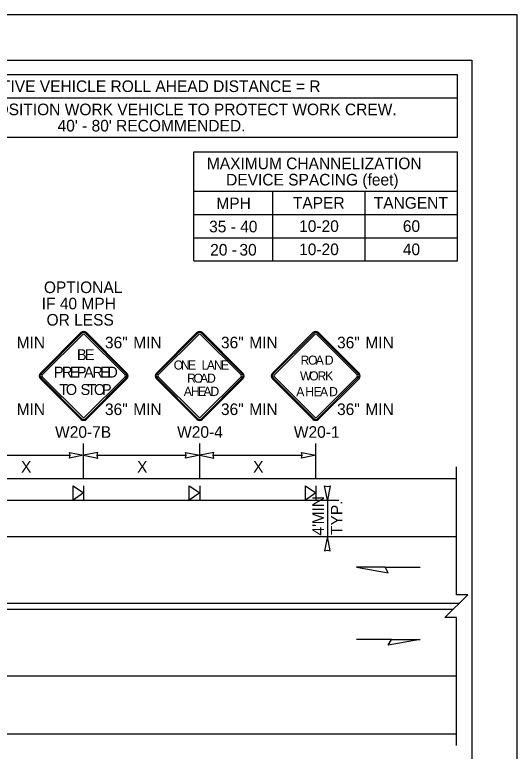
# Model space of a CAD drawing. Extents: x 99999.1 to 100095.7, y 99995 to 100010.7.
# Drawn here: x 100012.6 to 100016.06, y 100005.61 to 100010.69 of the extents above; entities that cross this region are included whole.
import ezdxf

# ---------------------------------------------------------------- set-up
doc = ezdxf.new("R2010")
doc.units = 0
for name, color, linetype in [('RD_ED_ShoulderPavedEdge', 7, 'Continuous'), ('RD_MK_LineDblYellowCenter', 7, 'Continuous'), ('RD_MK_LineEdgeWhite', 7, 'Continuous'), ('SH_GI_PlotLimits', 7, 'Continuous'), ('SH_GI_SheetBorder', 7, 'Continuous'), ('SH_TI_Tables', 7, 'Continuous'), ('TR_SN_ConstructionSigns', 7, 'Continuous'), ('TR_WZ_PortableSignMountBlk-Org', 7, 'Continuous'), ('TR_WZ_WorkZoneDetails', 7, 'Continuous'), ('TR_WZ_WorkZoneTextCurrent', 7, 'Continuous')]:
    doc.layers.add(name, color=color, linetype=linetype)

msp = doc.modelspace()

# ---------------------------------------------------------------- linework, layer by layer
at = {"layer": 'RD_ED_ShoulderPavedEdge'}
for p, q in [((100000.1076, 100007.4923), (100015.6424, 100007.4923)), ((100000.1076, 100005.7323), (100015.6424, 100005.7323))]:
    msp.add_line(p, q, dxfattribs=at)
at = {"layer": 'RD_MK_LineDblYellowCenter'}
for p, q in [((100012.2733, 100006.6323), (100015.6631, 100006.6323)), ((100012.2733, 100006.5923), (100015.6218, 100006.5923))]:
    msp.add_line(p, q, dxfattribs=at)
at = {"layer": 'RD_MK_LineEdgeWhite'}
for p, q in [((100000.1076, 100007.0923), (100015.6424, 100007.0923)), ((100000.1076, 100006.1323), (100015.6424, 100006.1323))]:
    msp.add_line(p, q, dxfattribs=at)
at = {"layer": 'SH_GI_PlotLimits'}
msp.add_lwpolyline([(99999.0625, 99999.6875), (100016.0625, 99999.6875), (100016.0625, 100010.6875), (99999.0625, 100010.6875)], close=True, dxfattribs=at)
at = {"layer": 'SH_GI_SheetBorder'}
for p, q in [((100000, 100010.375), (100015.75, 100010.375)), ((100015.75, 100010.375), (100015.75, 100000))]:
    msp.add_line(p, q, dxfattribs=at)
at = {"layer": 'SH_TI_Tables'}
for p, q in [((100011.4347, 100010.275), (100015.65, 100010.275)), ((100015.65, 100009.843), (100015.65, 100010.275)), ((100011.4347, 100010.115), (100015.65, 100010.115)), ((100011.4347, 100009.843), (100015.65, 100009.843)), ((100013.8318, 100009.743), (100015.65, 100009.743)), ((100013.8318, 100008.991), (100013.8318, 100009.743)), ((100015.65, 100008.991), (100015.65, 100009.743)), ((100013.8318, 100009.471), (100015.65, 100009.471)), ((100014.3773, 100008.991), (100014.3773, 100009.471)), ((100015.0136, 100008.991), (100015.0136, 100009.471)), ((100013.8318, 100009.311), (100014.3773, 100009.311)), ((100014.3773, 100009.311), (100015.0136, 100009.311)), ((100015.0136, 100009.311), (100015.65, 100009.311)), ((100013.8318, 100009.151), (100014.3773, 100009.151)), ((100014.3773, 100009.151), (100015.0136, 100009.151)), ((100015.0136, 100009.151), (100015.6472, 100009.151)), ((100013.8318, 100008.991), (100015.65, 100008.991))]:
    msp.add_line(p, q, dxfattribs=at)
at = {"layer": 'TR_SN_ConstructionSigns'}
for p, q in [((100013.0535, 100008.4972), (100012.775, 100008.2188)), ((100013.059, 100008.4917), (100012.7806, 100008.2132)), ((100013.3661, 100008.2132), (100013.0877, 100008.4917)), ((100013.3717, 100008.2188), (100013.0932, 100008.4972)), ((100013.8532, 100008.4972), (100013.5747, 100008.2188)), ((100013.8587, 100008.4917), (100013.5803, 100008.2132)), ((100014.1658, 100008.2132), (100013.8874, 100008.4917)), ((100014.1714, 100008.2188), (100013.8929, 100008.4972)), ((100014.6535, 100008.4972), (100014.375, 100008.2188)), ((100014.659, 100008.4917), (100014.3806, 100008.2132)), ((100014.9661, 100008.2132), (100014.6877, 100008.4917)), ((100014.9717, 100008.2188), (100014.6932, 100008.4972)), ((100012.7883, 100008.2055), (100013.0667, 100008.4839)), ((100013.08, 100008.4839), (100013.3584, 100008.2055)), ((100013.588, 100008.2055), (100013.8664, 100008.4839)), ((100013.8797, 100008.4839), (100014.1581, 100008.2055)), ((100014.3883, 100008.2055), (100014.6667, 100008.4839)), ((100014.68, 100008.4839), (100014.9584, 100008.2055)), ((100012.7806, 100008.1845), (100013.059, 100007.9061)), ((100013.0667, 100007.9138), (100012.7883, 100008.1923)), ((100013.3584, 100008.1923), (100013.08, 100007.9138)), ((100013.0877, 100007.9061), (100013.3661, 100008.1845)), ((100013.5803, 100008.1845), (100013.8587, 100007.9061)), ((100013.8664, 100007.9138), (100013.588, 100008.1923)), ((100014.1581, 100008.1923), (100013.8797, 100007.9138)), ((100013.8874, 100007.9061), (100014.1658, 100008.1845)), ((100014.3806, 100008.1845), (100014.659, 100007.9061)), ((100014.6667, 100007.9138), (100014.3883, 100008.1923)), ((100014.9584, 100008.1923), (100014.68, 100007.9138)), ((100014.6877, 100007.9061), (100014.9661, 100008.1845)), ((100012.775, 100008.179), (100013.0535, 100007.9006)), ((100013.0932, 100007.9006), (100013.3717, 100008.179)), ((100013.5747, 100008.179), (100013.8532, 100007.9006)), ((100013.8929, 100007.9006), (100014.1714, 100008.179)), ((100014.375, 100008.179), (100014.6535, 100007.9006)), ((100014.6932, 100007.9006), (100014.9717, 100008.179))]:
    msp.add_line(p, q, dxfattribs=at)
for centre, radius, start, end in [((100013.0733, 100008.4773), 0.0281, 45, 135), ((100013.0733, 100008.4773), 0.0203, 45, 135), ((100013.873, 100008.4773), 0.0281, 45, 135), ((100013.873, 100008.4773), 0.0203, 45, 135), ((100014.6733, 100008.4773), 0.0281, 45, 135), ((100014.6733, 100008.4773), 0.0203, 45, 135), ((100013.0733, 100008.4773), 0.00937, 45, 135), ((100013.873, 100008.4773), 0.00937, 45, 135), ((100014.6733, 100008.4773), 0.00937, 45, 135), ((100012.7949, 100008.1989), 0.0281, 135, 225), ((100012.7949, 100008.1989), 0.0203, 135, 225), ((100012.7949, 100008.1989), 0.00937, 135, 225), ((100013.3518, 100008.1989), 0.00937, 315, 45), ((100013.3518, 100008.1989), 0.0203, 315, 45), ((100013.3518, 100008.1989), 0.0281, 315, 45), ((100013.5946, 100008.1989), 0.0281, 135, 225), ((100013.5946, 100008.1989), 0.0203, 135, 225), ((100013.5946, 100008.1989), 0.00937, 135, 225), ((100014.1515, 100008.1989), 0.00937, 315, 45), ((100014.1515, 100008.1989), 0.0203, 315, 45), ((100014.1515, 100008.1989), 0.0281, 315, 45), ((100014.3949, 100008.1989), 0.0281, 135, 225), ((100014.3949, 100008.1989), 0.0203, 135, 225), ((100014.3949, 100008.1989), 0.00937, 135, 225), ((100014.9518, 100008.1989), 0.00937, 315, 45), ((100014.9518, 100008.1989), 0.0203, 315, 45), ((100014.9518, 100008.1989), 0.0281, 315, 45), ((100013.0733, 100007.9205), 0.0281, 225, 315), ((100013.0733, 100007.9205), 0.0203, 225, 315), ((100013.0733, 100007.9205), 0.00937, 225, 315), ((100013.873, 100007.9205), 0.0281, 225, 315), ((100013.873, 100007.9205), 0.0203, 225, 315), ((100013.873, 100007.9205), 0.00937, 225, 315), ((100014.6733, 100007.9205), 0.0281, 225, 315), ((100014.6733, 100007.9205), 0.0203, 225, 315), ((100014.6733, 100007.9205), 0.00937, 225, 315)]:
    msp.add_arc(centre, radius, start, end, dxfattribs=at)
at = {"layer": 'TR_WZ_PortableSignMountBlk-Org'}
for p, q in [((100013.0733, 100007.4422), (100013.0733, 100007.3422)), ((100013.8733, 100007.4422), (100013.8733, 100007.3422)), ((100014.6733, 100007.4422), (100014.6733, 100007.3422))]:
    msp.add_line(p, q, dxfattribs=at)
for points in [[(100013.0733, 100007.3923), (100013.0015, 100007.3422), (100013.0015, 100007.4422)], [(100013.8733, 100007.3923), (100013.8015, 100007.3422), (100013.8015, 100007.4422)], [(100014.6733, 100007.3923), (100014.6015, 100007.3422), (100014.6015, 100007.4422)]]:
    msp.add_lwpolyline(points, close=True, dxfattribs=at)
at = {"layer": 'TR_WZ_WorkZoneDetails'}
for p, q in [((100013.0733, 100007.4923), (100013.0733, 100007.7323)), ((100013.8733, 100007.4923), (100013.8733, 100007.7323)), ((100014.6733, 100007.4921), (100014.6733, 100007.7323)), ((100012.3671, 100007.6523), (100012.9796, 100007.6523)), ((100013.1671, 100007.6523), (100013.7796, 100007.6523)), ((100013.9671, 100007.6523), (100014.5796, 100007.6523)), ((100012.2733, 100007.3422), (100014.6733, 100007.3422)), ((100014.6733, 100007.3422), (100014.8333, 100007.3422)), ((100014.7533, 100007.3422), (100014.7533, 100007.0923)), ((100014.6733, 100007.0923), (100014.8333, 100007.0923)), ((100015.1513, 100006.8816), (100015.3924, 100006.8816)), ((100015.1959, 100006.3816), (100014.9548, 100006.3816))]:
    msp.add_line(p, q, dxfattribs=at)
for points in [[(100013.0733, 100007.6523), (100012.9751, 100007.6331), (100012.9796, 100007.6523), (100012.9751, 100007.6716)], [(100013.0733, 100007.6523), (100013.1716, 100007.6331), (100013.1671, 100007.6523), (100013.1716, 100007.6716)], [(100013.8733, 100007.6523), (100013.7751, 100007.6331), (100013.7796, 100007.6523), (100013.7751, 100007.6716)], [(100013.8733, 100007.6523), (100013.9716, 100007.6331), (100013.9671, 100007.6523), (100013.9716, 100007.6716)], [(100014.6733, 100007.6523), (100014.5751, 100007.6331), (100014.5796, 100007.6523), (100014.5751, 100007.6716)], [(100014.7533, 100007.3422), (100014.7341, 100007.4405), (100014.7533, 100007.436), (100014.7726, 100007.4405)], [(100014.7533, 100007.0923), (100014.7341, 100006.9941), (100014.7533, 100006.9986), (100014.7726, 100006.9941)], [(100014.9548, 100006.8816), (100015.1736, 100006.843), (100015.1513, 100006.8816)], [(100015.3924, 100006.3816), (100015.1736, 100006.343), (100015.1959, 100006.3816)]]:
    msp.add_lwpolyline(points, close=True, dxfattribs=at)
msp.add_lwpolyline([(100015.6424, 100005.6523), (100015.6424, 100006.5349), (100015.5624, 100006.5349), (100015.7225, 100006.6898), (100015.6424, 100006.6898), (100015.6424, 100007.5723)], dxfattribs=at)

# ---------------------------------------------------------------- texts
at = {"layer": 'SH_TI_Tables'}
for s, p in [('PROTECTIVE VEHICLE ROLL AHEAD DISTANCE = R', (100012.0577, 100010.155)), ('STRATEGICALLY POSITION WORK VEHICLE TO PROTECT WORK CREW.', (100011.4984, 100009.995)), ("40' - 80'", (100012.8935, 100009.883)), ('RECOMMENDED.', (100013.297, 100009.883))]:
    msp.add_text(s, height=0.08, rotation=360, dxfattribs=at).set_placement(p)
for s, p in [('MAXIMUM CHANNELIZATION', (100013.9227, 100009.623)), ('DEVICE SPACING (feet)', (100014.0553, 100009.511)), ('MPH', (100013.9878, 100009.3479)), ('TAPER', (100014.5157, 100009.351)), ('TANGENT', (100015.0731, 100009.351)), ('35', (100013.9381, 100009.1879)), ('- 40', (100014.0869, 100009.1879)), ('10-20', (100014.5588, 100009.191)), ('60', (100015.2737, 100009.191)), ('20', (100013.9456, 100009.0279)), ('30', (100014.1472, 100009.0279)), ('10-20', (100014.5588, 100009.031)), ('40', (100015.2737, 100009.031)), ('-', (100014.0944, 100009.0279))]:
    msp.add_text(s, height=0.08, dxfattribs=at).set_placement(p)
at = {"layer": 'TR_SN_ConstructionSigns'}
for s, height, p in [('OPTIONAL', 0.08, (100012.7994, 100008.7694)), ('IF 40 MPH', 0.08, (100012.7843, 100008.6574)), ('OR LESS', 0.08, (100012.8175, 100008.5454)), ('B', 0.075, (100013.0271, 100008.3074)), ('E', 0.075, (100013.0814, 100008.3074)), ('R', 0.0625, (100014.5683, 100008.2762)), ('O', 0.0625, (100014.6204, 100008.2762)), ('A', 0.0625, (100014.6732, 100008.2762)), ('D', 0.0625, (100014.7359, 100008.2762)), ('O', 0.0625, (100013.6943, 100008.2426)), ('N', 0.0625, (100013.7437, 100008.2426)), ('E', 0.0625, (100013.7924, 100008.2426)), ('L', 0.0625, (100013.8868, 100008.2426)), ('A', 0.0625, (100013.9224, 100008.2426)), ('N', 0.0625, (100013.9712, 100008.2426)), ('E', 0.0625, (100014.0199, 100008.2426)), ('P', 0.075, (100012.8684, 100008.1874)), ('R', 0.075, (100012.9237, 100008.1874)), ('E', 0.075, (100012.9769, 100008.1874)), ('P', 0.075, (100013.0264, 100008.1874)), ('A', 0.075, (100013.0763, 100008.1874)), ('R', 0.075, (100013.1335, 100008.1874)), ('E', 0.075, (100013.1868, 100008.1874)), ('D', 0.075, (100013.2362, 100008.1874)), ('R', 0.0625, (100013.7868, 100008.152)), ('O', 0.0625, (100013.8312, 100008.152)), ('A', 0.0625, (100013.8755, 100008.152)), ('D', 0.0625, (100013.9243, 100008.152)), ('W', 0.0625, (100014.565, 100008.1676)), ('O', 0.0625, (100014.6282, 100008.1676)), ('R', 0.0625, (100014.6855, 100008.1676)), ('K', 0.0625, (100014.7379, 100008.1676)), ('T', 0.075, (100012.9051, 100008.0674)), ('O', 0.075, (100012.9502, 100008.0674)), ('S', 0.075, (100013.0516, 100008.0674)), ('T', 0.075, (100013.0988, 100008.0674)), ('O', 0.075, (100013.1439, 100008.0674)), ('P', 0.075, (100013.1996, 100008.0674)), ('A', 0.0625, (100013.7637, 100008.0614)), ('H', 0.0625, (100013.8124, 100008.0614)), ('E', 0.0625, (100013.8612, 100008.0614)), ('A', 0.0625, (100013.8987, 100008.0614)), ('D', 0.0625, (100013.9474, 100008.0614)), ('A', 0.0625, (100014.539, 100008.0591)), ('H', 0.0625, (100014.6015, 100008.0591)), ('E', 0.0625, (100014.659, 100008.0591)), ('A', 0.0625, (100014.7027, 100008.0591)), ('D', 0.0625, (100014.7652, 100008.0591))]:
    msp.add_text(s, height=height, dxfattribs=at).set_placement(p)
for s, p in [('MIN', (100012.6114, 100008.3887)), ('36"', (100013.2201, 100008.3887)), ('MIN', (100013.4151, 100008.3887)), ('36"', (100014.0198, 100008.3887)), ('MIN', (100014.2148, 100008.3887)), ('36"', (100014.8201, 100008.3887)), ('MIN', (100015.0151, 100008.3887)), ('MIN', (100012.6114, 100007.9291)), ('36"', (100013.2201, 100007.9291)), ('MIN', (100013.4151, 100007.9291)), ('36"', (100014.0198, 100007.9291)), ('MIN', (100014.2148, 100007.9291)), ('36"', (100014.8201, 100007.9291)), ('MIN', (100015.0151, 100007.9291)), ('W20-7B', (100012.8763, 100007.7723)), ('W20-4', (100013.7176, 100007.7723)), ('W20-1', (100014.5224, 100007.7723))]:
    msp.add_text(s, height=0.08, rotation=360, dxfattribs=at).set_placement(p)
at = {"layer": 'TR_WZ_WorkZoneTextCurrent'}
for p in [(100012.6416, 100007.5323), (100013.4416, 100007.5323), (100014.2416, 100007.5323)]:
    msp.add_text('X', height=0.08, dxfattribs=at).set_placement(p)
for s, p in [('MIN', (100014.7293, 100007.1754)), ('TYP.', (100014.8573, 100007.1026)), ("4'", (100014.7293, 100007.0989))]:
    msp.add_text(s, height=0.08, rotation=90, dxfattribs=at).set_placement(p)

doc.saveas('drawing.dxf')
